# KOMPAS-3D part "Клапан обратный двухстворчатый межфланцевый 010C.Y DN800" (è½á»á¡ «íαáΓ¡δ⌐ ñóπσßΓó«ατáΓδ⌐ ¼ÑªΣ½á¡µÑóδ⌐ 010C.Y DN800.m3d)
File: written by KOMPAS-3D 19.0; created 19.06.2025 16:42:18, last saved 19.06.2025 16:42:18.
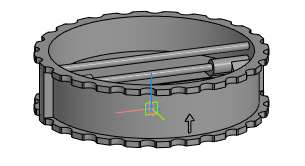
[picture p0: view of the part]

Document properties: Полное имя файла: E:\Dendor Работа Сачек\3D для проектировщиков\5.2 Тип 010C, 010C.Y Клапан обратный двухстворчатый межфланцевый\stp_Клапан обратный двухстворчатый межфланцевый 010C.Y\Клапан обратный двухстворчатый межфланцевый 010C.Y DN800.m3d

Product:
- Part/product: Клапан обратный двухстворчатый межфланцевый 010C.Y DN800

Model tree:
1. Операция без истории:1  (labels: Клапан обратный двухстворчатый межфланцевый 010C.Y DN800)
